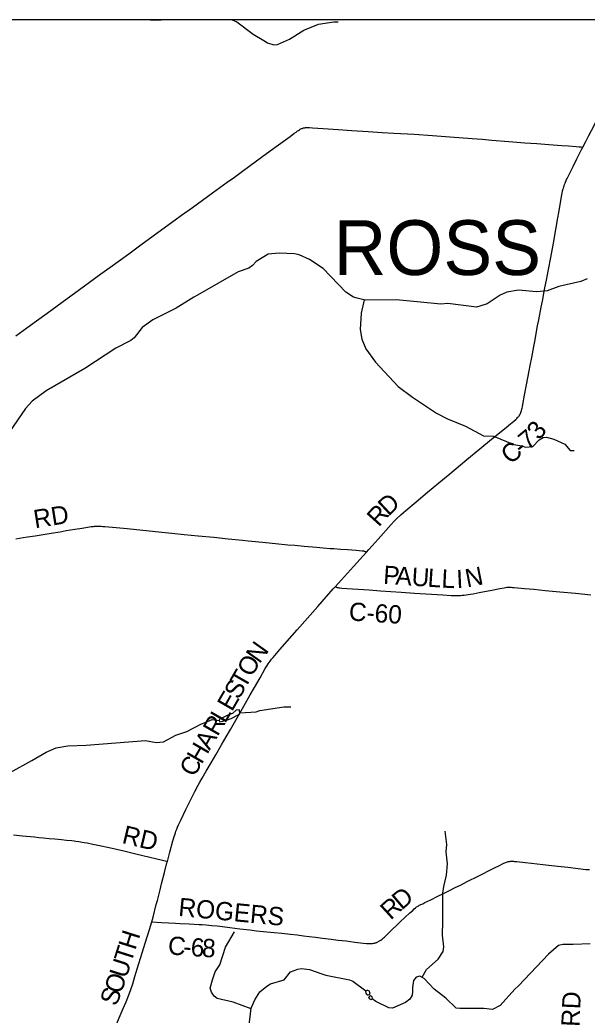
# Model space of a CAD drawing. Extents: x -49 to -8.2, y 9.4 to 23.5.
# Drawn here: x -44.254 to -43.371, y 19.456 to 21.004 of the extents above; entities that cross this region are included whole.
import ezdxf

# ---------------------------------------------------------------- set-up
doc = ezdxf.new("R2010")
doc.units = 0
for name, color, linetype in [('GM_X_Adjacent_County', 7, 'Continuous'), ('GM_X_County_Road', 7, 'Continuous'), ('GM_X_County_Road_Text', 7, 'Continuous'), ('GM_X_Major_River', 7, 'Continuous'), ('GM_X_Minor_Lake', 7, 'Continuous'), ('GM_X_Minor_River', 7, 'Continuous'), ('GM_X_Township', 7, 'Continuous'), ('GM_X_Township_Road', 7, 'Continuous'), ('GM_X_Township_Road_Text', 7, 'Continuous'), ('GM_X_Township_Text', 7, 'Continuous')]:
    doc.layers.add(name, color=color, linetype=linetype)

msp = doc.modelspace()

# ---------------------------------------------------------------- linework, layer by layer
at = {"layer": 'GM_X_Adjacent_County'}
msp.add_lwpolyline([(-42.0989, 21.0039), (-46.2895, 21.0039), (-46.2895, 15.4273)], dxfattribs=at)
at = {"layer": 'GM_X_County_Road'}
for points in [[(-43.378, 20.806), (-43.3735, 20.815), (-43.3689, 20.824), (-43.3607, 20.8398), (-43.3541, 20.8524), (-43.3514, 20.8577), (-43.3468, 20.8665), (-43.3433, 20.8731), (-43.3378, 20.8839), (-43.3284, 20.9017), (-43.3198, 20.918), (-43.3147, 20.9274)], [(-44.2603, 20.5123), (-44.2432, 20.5249), (-44.2282, 20.5358), (-44.2119, 20.5477), (-44.1885, 20.5647), (-44.1612, 20.5847), (-44.1459, 20.5959), (-44.128, 20.6088), (-44.1142, 20.6188), (-44.0976, 20.6308), (-44.0844, 20.6402), (-44.0657, 20.6541), (-44.0275, 20.6819), (-44.0123, 20.6927), (-44.0026, 20.6999), (-43.9855, 20.7123), (-43.9545, 20.7347), (-43.9314, 20.7515), (-43.9203, 20.7594), (-43.9099, 20.7669), (-43.8959, 20.7772), (-43.8779, 20.7904), (-43.8645, 20.8), (-43.8515, 20.8095), (-43.8445, 20.8147), (-43.8337, 20.8226), (-43.8276, 20.8272), (-43.8244, 20.8295), (-43.8234, 20.8303), (-43.8221, 20.8312), (-43.8207, 20.8321), (-43.819, 20.8331), (-43.8178, 20.8338), (-43.8168, 20.8343), (-43.8157, 20.8348), (-43.8147, 20.8352), (-43.8137, 20.8355), (-43.8126, 20.8358), (-43.8117, 20.836), (-43.8107, 20.8362), (-43.8097, 20.8363), (-43.8088, 20.8364), (-43.8076, 20.8364), (-43.8056, 20.8364), (-43.8032, 20.8363), (-43.7986, 20.836), (-43.7821, 20.8348), (-43.7586, 20.8332), (-43.7378, 20.832), (-43.7121, 20.8304), (-43.6904, 20.8289), (-43.6724, 20.8279), (-43.6405, 20.826), (-43.6119, 20.8241), (-43.5853, 20.8221), (-43.5503, 20.8194), (-43.5348, 20.8182), (-43.5196, 20.817), (-43.4933, 20.8149), (-43.4685, 20.8129), (-43.4496, 20.8115), (-43.4311, 20.8102), (-43.4109, 20.8086), (-43.4004, 20.8078), (-43.3883, 20.807), (-43.3839, 20.8066), (-43.3809, 20.8063), (-43.378, 20.806)], [(-43.7146, 20.176), (-43.711, 20.1801), (-43.7058, 20.1858), (-43.6968, 20.1961), (-43.6766, 20.2189), (-43.6719, 20.2239), (-43.6698, 20.2261), (-43.6677, 20.2281), (-43.6615, 20.2338), (-43.6573, 20.2374), (-43.6535, 20.2407), (-43.6374, 20.2543), (-43.6197, 20.2691), (-43.6021, 20.2838), (-43.5851, 20.2979), (-43.5586, 20.3199), (-43.5382, 20.3367), (-43.5201, 20.3514), (-43.4999, 20.3679), (-43.4907, 20.3753), (-43.4878, 20.3777), (-43.4852, 20.3798), (-43.4821, 20.3825), (-43.481, 20.3836), (-43.4795, 20.3851), (-43.4785, 20.3862), (-43.4778, 20.3871), (-43.4771, 20.3881), (-43.4763, 20.3895), (-43.4756, 20.3907), (-43.475, 20.3918), (-43.4744, 20.3933), (-43.4739, 20.3948), (-43.4734, 20.3965), (-43.4729, 20.3982), (-43.4725, 20.3998), (-43.4721, 20.4019), (-43.4714, 20.4056), (-43.4687, 20.4202), (-43.4658, 20.4361), (-43.4617, 20.4581), (-43.4602, 20.4661), (-43.4577, 20.4789), (-43.4545, 20.4957), (-43.4525, 20.5063), (-43.4506, 20.5161), (-43.4484, 20.528), (-43.4466, 20.5375), (-43.4428, 20.557), (-43.4409, 20.5664), (-43.4381, 20.5814), (-43.437, 20.5872), (-43.4348, 20.5991), (-43.4317, 20.6156), (-43.4281, 20.6344), (-43.4239, 20.6568), (-43.4201, 20.6779), (-43.4169, 20.6959), (-43.4154, 20.7045), (-43.4134, 20.7161), (-43.4113, 20.729), (-43.4103, 20.7345), (-43.4097, 20.7376), (-43.4095, 20.7383), (-43.4094, 20.7389), (-43.4091, 20.74), (-43.4087, 20.7413), (-43.4084, 20.7424), (-43.4079, 20.7441), (-43.4073, 20.746), (-43.4066, 20.7479), (-43.4058, 20.75), (-43.4052, 20.7517), (-43.4042, 20.754), (-43.4035, 20.7554), (-43.4027, 20.757), (-43.3978, 20.7667), (-43.3932, 20.7759), (-43.3872, 20.7877), (-43.3799, 20.8022), (-43.378, 20.806)], [(-43.7635, 20.1219), (-43.7539, 20.1326), (-43.7348, 20.1538), (-43.7146, 20.176)], [(-44.0246, 19.6947), (-44.0209, 19.7091), (-44.0161, 19.7265), (-44.0151, 19.73), (-44.014, 19.7333), (-44.0132, 19.736), (-44.0122, 19.739), (-44.0112, 19.7419), (-44.0099, 19.7451), (-44.0087, 19.7482), (-44.0072, 19.7517), (-44.0057, 19.755), (-44.0038, 19.7591), (-43.996, 19.7753), (-43.9876, 19.7923), (-43.982, 19.8037), (-43.9767, 19.8136), (-43.9742, 19.8182), (-43.9706, 19.8245), (-43.9643, 19.8352), (-43.9567, 19.848), (-43.9491, 19.8608), (-43.9404, 19.8759), (-43.9332, 19.8883), (-43.9265, 19.8998), (-43.9162, 19.9179), (-43.9055, 19.9365), (-43.8956, 19.954), (-43.8891, 19.9653), (-43.8804, 19.9804), (-43.8723, 19.9948), (-43.8694, 19.9995), (-43.8678, 20.0019), (-43.8662, 20.0042), (-43.8644, 20.0065), (-43.8624, 20.0092), (-43.8602, 20.012), (-43.8575, 20.0152), (-43.8495, 20.0243), (-43.8226, 20.0548), (-43.7906, 20.0913), (-43.7664, 20.1187), (-43.7635, 20.1219)], [(-43.7635, 20.1219), (-43.7621, 20.1214), (-43.7613, 20.1212), (-43.7604, 20.1209), (-43.7592, 20.1207), (-43.7579, 20.1204), (-43.7564, 20.1202), (-43.7533, 20.1199), (-43.7363, 20.1187), (-43.7108, 20.117), (-43.6929, 20.1157), (-43.6606, 20.1135), (-43.6398, 20.1122), (-43.5958, 20.1093), (-43.5831, 20.1085), (-43.5775, 20.1083), (-43.5755, 20.1084), (-43.5735, 20.1084), (-43.571, 20.1084), (-43.5685, 20.1086), (-43.566, 20.1087), (-43.5629, 20.109), (-43.5598, 20.1094), (-43.5565, 20.1098), (-43.5527, 20.1104), (-43.5488, 20.1111), (-43.5394, 20.113), (-43.5199, 20.1169), (-43.5071, 20.1195), (-43.5007, 20.1206), (-43.4982, 20.121), (-43.4965, 20.1212), (-43.4949, 20.1213), (-43.4931, 20.1214), (-43.4915, 20.1214), (-43.4898, 20.1213), (-43.4873, 20.1211), (-43.4848, 20.1209), (-43.4688, 20.1195), (-43.4542, 20.1181), (-43.4369, 20.1164), (-43.414, 20.1143), (-43.3896, 20.112), (-43.3658, 20.1097)], [(-44.0487, 19.6007), (-44.0338, 19.5997), (-44.0228, 19.599), (-44.0121, 19.5985), (-44.0049, 19.5982), (-43.9906, 19.5975), (-43.9754, 19.5968), (-43.9704, 19.5965), (-43.9645, 19.5961), (-43.9599, 19.5956), (-43.9553, 19.5952), (-43.947, 19.5943), (-43.9388, 19.5933), (-43.9276, 19.592), (-43.9121, 19.59), (-43.8963, 19.5881), (-43.8859, 19.5869), (-43.8696, 19.5853), (-43.8585, 19.5842), (-43.8464, 19.5829), (-43.8337, 19.5816), (-43.8224, 19.5803), (-43.8128, 19.5791), (-43.8038, 19.578), (-43.7942, 19.5767), (-43.7832, 19.5754), (-43.7699, 19.5738), (-43.7586, 19.5724), (-43.7466, 19.571), (-43.733, 19.5693), (-43.72, 19.5678), (-43.7147, 19.5672), (-43.7116, 19.5669), (-43.7093, 19.5668), (-43.7078, 19.5668), (-43.7065, 19.5669), (-43.7052, 19.5671), (-43.704, 19.5674), (-43.7019, 19.5678), (-43.7008, 19.5681), (-43.6997, 19.5685), (-43.6989, 19.5687), (-43.6981, 19.5691), (-43.6971, 19.5695), (-43.6962, 19.57), (-43.6953, 19.5705), (-43.6943, 19.571), (-43.6933, 19.5717), (-43.6922, 19.5724), (-43.6905, 19.5737), (-43.6881, 19.5757), (-43.6865, 19.5771), (-43.6797, 19.5839), (-43.6741, 19.5894), (-43.6682, 19.5952), (-43.6616, 19.6013), (-43.6549, 19.6075), (-43.6473, 19.6146), (-43.6428, 19.6186), (-43.6403, 19.6209), (-43.6385, 19.6223), (-43.6372, 19.6234), (-43.6366, 19.6239), (-43.6358, 19.6244), (-43.6345, 19.6253), (-43.6332, 19.626), (-43.6304, 19.6275), (-43.6272, 19.629), (-43.6239, 19.6307), (-43.6148, 19.6351), (-43.605, 19.64), (-43.595, 19.6449), (-43.5856, 19.6497), (-43.5767, 19.6541), (-43.5686, 19.658), (-43.5579, 19.6634), (-43.541, 19.6719), (-43.5338, 19.6754), (-43.5249, 19.6799), (-43.5144, 19.6851), (-43.5086, 19.6881), (-43.5011, 19.6919), (-43.4997, 19.6925), (-43.4982, 19.6931), (-43.4969, 19.6936), (-43.4955, 19.6941), (-43.4942, 19.6944), (-43.4936, 19.6945), (-43.4931, 19.6946), (-43.492, 19.6948), (-43.4907, 19.6949), (-43.4895, 19.695), (-43.4885, 19.695), (-43.4876, 19.695), (-43.486, 19.6949), (-43.4845, 19.6948), (-43.4834, 19.6948), (-43.4807, 19.6946), (-43.4678, 19.6932), (-43.4581, 19.6921), (-43.4405, 19.6901), (-43.4171, 19.6874), (-43.4014, 19.6856), (-43.3853, 19.6838), (-43.3733, 19.6824), (-43.3675, 19.6819)], [(-44.0487, 19.6007), (-44.0469, 19.6078), (-44.0418, 19.6276), (-44.0402, 19.634), (-44.038, 19.6423), (-44.0359, 19.6503), (-44.0335, 19.6599), (-44.0291, 19.6773), (-44.0252, 19.6926), (-44.0246, 19.6947)], [(-44.1213, 19.4002), (-44.114, 19.4176), (-44.1069, 19.4342), (-44.0932, 19.4658), (-44.0888, 19.4764), (-44.0852, 19.4857), (-44.0817, 19.4953), (-44.0786, 19.5045), (-44.0752, 19.5157), (-44.071, 19.5294), (-44.059, 19.5673), (-44.0524, 19.5887), (-44.0487, 19.6007)]]:
    msp.add_lwpolyline(points, dxfattribs=at)
at = {"layer": 'GM_X_Major_River'}
for points in [[(-43.3669, 19.5666), (-43.3929, 19.5654), (-43.4093, 19.5655), (-43.416, 19.5641), (-43.4314, 19.5506), (-43.4784, 19.501), (-43.4839, 19.4958), (-43.5068, 19.4705), (-43.5188, 19.4643), (-43.5322, 19.466), (-43.5693, 19.4657), (-43.5751, 19.4662), (-43.5915, 19.4822), (-43.6095, 19.4959), (-43.6249, 19.5127), (-43.6318, 19.5163), (-43.6375, 19.5149), (-43.6418, 19.5095), (-43.643, 19.4987), (-43.6431, 19.4922), (-43.6438, 19.4867), (-43.6473, 19.4805), (-43.654, 19.475), (-43.6741, 19.4664), (-43.6799, 19.4669), (-43.7004, 19.4767), (-43.7061, 19.4808)], [(-43.9634, 19.3196), (-43.9479, 19.336), (-43.9178, 19.3778), (-43.9116, 19.3915), (-43.9093, 19.4028), (-43.9058, 19.41), (-43.9053, 19.4153), (-43.8977, 19.4358), (-43.8943, 19.4662), (-43.8887, 19.4795), (-43.8805, 19.4917), (-43.8697, 19.5004), (-43.864, 19.5041), (-43.8427, 19.5107), (-43.8332, 19.523), (-43.8217, 19.5272), (-43.8157, 19.528), (-43.8036, 19.5268), (-43.7844, 19.5196), (-43.778, 19.5177), (-43.7411, 19.5105), (-43.7362, 19.5085), (-43.7159, 19.4933)], [(-43.7159, 19.4933), (-43.7163, 19.4919), (-43.716, 19.4899), (-43.7149, 19.4884), (-43.7136, 19.4872), (-43.7119, 19.4872), (-43.71, 19.4879), (-43.7092, 19.4892), (-43.7093, 19.4909), (-43.7101, 19.4928), (-43.7115, 19.4935), (-43.7127, 19.4938), (-43.714, 19.4938), (-43.7144, 19.4937)], [(-43.7159, 19.4933), (-43.7144, 19.4937)], [(-43.7116, 19.4832), (-43.711, 19.4824), (-43.7099, 19.481), (-43.7086, 19.4802), (-43.7075, 19.48), (-43.7065, 19.4804), (-43.7059, 19.481), (-43.7053, 19.4827), (-43.7057, 19.484), (-43.7072, 19.4848), (-43.7087, 19.4854), (-43.7095, 19.4852)], [(-43.7095, 19.4852), (-43.7116, 19.4832)]]:
    msp.add_lwpolyline(points, dxfattribs=at)
at = {"layer": 'GM_X_Minor_Lake'}
for points in [[(-43.9429, 19.9117), (-43.9326, 19.9143), (-43.9253, 19.917), (-43.9146, 19.9226), (-43.9116, 19.9246), (-43.9124, 19.9307), (-43.9177, 19.93), (-43.9235, 19.9246), (-43.9304, 19.9223), (-43.9386, 19.9182), (-43.9428, 19.9162)], [(-43.9428, 19.9162), (-43.9434, 19.9156), (-43.9438, 19.9145), (-43.9436, 19.9126), (-43.9429, 19.9117)], [(-43.9634, 19.3196), (-43.9479, 19.336), (-43.9178, 19.3778), (-43.9116, 19.3915), (-43.9093, 19.4028), (-43.9058, 19.41), (-43.9053, 19.4153), (-43.8977, 19.4358), (-43.8943, 19.4662), (-43.8887, 19.4795), (-43.8805, 19.4917), (-43.8697, 19.5004), (-43.864, 19.5041), (-43.8427, 19.5107), (-43.8332, 19.523), (-43.8217, 19.5272), (-43.8157, 19.528), (-43.8036, 19.5268), (-43.7844, 19.5196), (-43.778, 19.5177), (-43.7411, 19.5105), (-43.7362, 19.5085), (-43.7159, 19.4933)]]:
    msp.add_lwpolyline(points, dxfattribs=at)
at = {"layer": 'GM_X_Minor_River'}
for points in [[(-44.0516, 21.0039), (-44.0464, 21.0033), (-44.0342, 21.0039)], [(-43.9237, 21.0039), (-43.9165, 21.0009), (-43.8909, 20.9819), (-43.8746, 20.9719), (-43.869, 20.968), (-43.8588, 20.9653), (-43.8533, 20.9654), (-43.8347, 20.974), (-43.8121, 20.9882), (-43.7892, 20.9975), (-43.7657, 21.001), (-43.7587, 21.0007)], [(-43.3715, 20.6009), (-43.3812, 20.5967), (-43.4153, 20.5889), (-43.4334, 20.5823), (-43.4503, 20.5809), (-43.4783, 20.5835), (-43.4965, 20.5802), (-43.5066, 20.5756), (-43.527, 20.5623), (-43.5382, 20.5584), (-43.5433, 20.5569), (-43.5881, 20.5627), (-43.5992, 20.5619), (-43.6309, 20.565), (-43.6686, 20.5682), (-43.7163, 20.5679), (-43.7231, 20.5694), (-43.7293, 20.5712), (-43.7352, 20.5724), (-43.7468, 20.5804), (-43.782, 20.6173), (-43.8035, 20.631), (-43.8193, 20.6385), (-43.8267, 20.6402), (-43.8507, 20.641), (-43.8676, 20.6396), (-43.8864, 20.6278), (-43.8923, 20.6218), (-43.8981, 20.6176), (-43.9147, 20.6118), (-43.9777, 20.5757), (-43.9832, 20.5728), (-44.0108, 20.5553), (-44.047, 20.5371), (-44.0638, 20.5255), (-44.0761, 20.5093), (-44.0813, 20.5049), (-44.1046, 20.4932), (-44.1533, 20.4618), (-44.2132, 20.427), (-44.2349, 20.4106), (-44.2455, 20.3996), (-44.2704, 20.3629)], [(-43.7186, 20.5684), (-43.7228, 20.5475), (-43.7245, 20.5223), (-43.7221, 20.5074), (-43.7156, 20.4923), (-43.7006, 20.4715), (-43.6657, 20.4334), (-43.6434, 20.4171), (-43.606, 20.3921), (-43.5889, 20.3834), (-43.5608, 20.3721), (-43.5329, 20.3569), (-43.5172, 20.3562), (-43.4857, 20.3435), (-43.4729, 20.3414), (-43.4673, 20.3392), (-43.4559, 20.3401), (-43.446, 20.3508), (-43.4397, 20.3544), (-43.4348, 20.3547), (-43.4233, 20.3515), (-43.4063, 20.3441), (-43.3978, 20.3341), (-43.3917, 20.334)], [(-43.9118, 19.926), (-43.8865, 19.9274), (-43.8806, 19.9295), (-43.8432, 19.9353), (-43.8324, 19.9353)], [(-44.4085, 19.7863), (-44.3863, 19.7917), (-44.3355, 19.817), (-44.3229, 19.8213), (-44.2694, 19.8331), (-44.2354, 19.8518), (-44.2133, 19.8647), (-44.1979, 19.8715), (-44.1794, 19.8748), (-44.1512, 19.8754), (-44.0584, 19.883), (-44.042, 19.8798), (-44.0304, 19.881), (-44.0113, 19.8913), (-43.9945, 19.897), (-43.9715, 19.9086), (-43.9656, 19.9106), (-43.9551, 19.9155), (-43.9437, 19.9141)], [(-43.6282, 19.5144), (-43.6212, 19.5267), (-43.6033, 19.5425), (-43.5955, 19.5545), (-43.5946, 19.5621), (-43.5965, 19.5802), (-43.5962, 19.6011), (-43.5958, 19.6452), (-43.5946, 19.6558), (-43.5901, 19.6732), (-43.5887, 19.691), (-43.5906, 19.7097), (-43.5899, 19.7209), (-43.5925, 19.7416)], [(-43.8943, 19.4656), (-43.9222, 19.4759), (-43.9469, 19.4817), (-43.9518, 19.485), (-43.9562, 19.4912), (-43.9578, 19.4977), (-43.9544, 19.5105), (-43.9502, 19.5228), (-43.943, 19.5337), (-43.9342, 19.5613), (-43.9203, 19.585)]]:
    msp.add_lwpolyline(points, dxfattribs=at)
at = {"layer": 'GM_X_Township'}
msp.add_line((-42.0989, 21.0039), (-44.9675, 21.0039), dxfattribs=at)
at = {"layer": 'GM_X_Township_Road'}
for points in [[(-44.2605, 20.1965), (-44.2488, 20.1985), (-44.2424, 20.1995), (-44.2304, 20.2015), (-44.2178, 20.2035), (-44.2056, 20.2054), (-44.1915, 20.2077), (-44.182, 20.2093), (-44.1688, 20.2115), (-44.1571, 20.2134), (-44.1431, 20.2156), (-44.1412, 20.2158), (-44.1395, 20.216), (-44.1381, 20.2162), (-44.1369, 20.2162), (-44.1357, 20.2163), (-44.134, 20.2163), (-44.1322, 20.2163), (-44.1299, 20.2163), (-44.1275, 20.2162), (-44.1249, 20.216), (-44.122, 20.2158), (-44.1043, 20.2141), (-44.0873, 20.2125), (-44.0626, 20.21), (-44.028, 20.2065), (-44.0178, 20.2055), (-43.9986, 20.2035), (-43.9766, 20.2014), (-43.9525, 20.199), (-43.93, 20.1968), (-43.9077, 20.1945), (-43.8991, 20.1936), (-43.8932, 20.193), (-43.8876, 20.1925), (-43.8713, 20.1907), (-43.8561, 20.1892), (-43.8369, 20.1875), (-43.8265, 20.1865), (-43.8115, 20.1852), (-43.7928, 20.1836), (-43.782, 20.1827), (-43.7712, 20.1818), (-43.7657, 20.1814), (-43.755, 20.1807), (-43.7441, 20.1799), (-43.731, 20.1789), (-43.7216, 20.178), (-43.7204, 20.1779), (-43.7195, 20.1777), (-43.7184, 20.1775), (-43.7177, 20.1773), (-43.7161, 20.1767), (-43.7146, 20.176)], [(-44.2642, 19.7363), (-44.25, 19.7347), (-44.2312, 19.7328), (-44.2247, 19.7321), (-44.2173, 19.7315), (-44.2086, 19.7306), (-44.1996, 19.7297), (-44.1894, 19.7287), (-44.1817, 19.728), (-44.1733, 19.7271), (-44.1697, 19.7267), (-44.1669, 19.7263), (-44.1625, 19.7257), (-44.16, 19.7254), (-44.157, 19.7249), (-44.1539, 19.7244), (-44.1493, 19.7235), (-44.1405, 19.7217), (-44.1302, 19.7195), (-44.1153, 19.7162), (-44.0926, 19.711), (-44.0738, 19.7067), (-44.0626, 19.7041), (-44.0323, 19.6966), (-44.0283, 19.6956), (-44.0246, 19.6947)]]:
    msp.add_lwpolyline(points, dxfattribs=at)

# ---------------------------------------------------------------- texts
at = {"layer": 'GM_X_County_Road_Text'}
for s, height, rotation, p in [('3', 0.0284, 50.5743, (-43.446, 20.349)), ('7', 0.0284, 39.4159, (-43.4638, 20.3336)), ('C', 0.0284, 39.1584, (-43.4911, 20.3114)), ('-', 0.0284, 39.1877, (-43.473, 20.3261)), ('D', 0.0284, 42.9801, (-43.6806, 20.2309)), ('R', 0.0284, 48.0041, (-43.6957, 20.214)), ('P', 0.0284, 356.215, (-43.6893, 20.1267)), ('A', 0.0284, 356.2123, (-43.6702, 20.1255)), ('U', 0.0284, 356.2149, (-43.6452, 20.1238)), ('L', 0.0284, 356.2486, (-43.6203, 20.1222)), ('L', 0.0284, 357.1496, (-43.5986, 20.1208)), ('I', 0.0284, 2.7323, (-43.5743, 20.1197)), ('N', 0.0284, 11.0056, (-43.5582, 20.1208)), ('C-60', 0.02841, 356.23, (-43.7428, 20.0697)), ('N', 0.0284, 54.583, (-43.8812, 20.0012)), ('O', 0.0284, 59.9971, (-43.8934, 19.9802)), ('T', 0.0284, 60.0444, (-43.904, 19.9618)), ('S', 0.0284, 60.0394, (-43.9135, 19.9452)), ('E', 0.0284, 60.0444, (-43.9241, 19.9267)), ('L', 0.0284, 60.0444, (-43.9348, 19.9083)), ('R', 0.0284, 60.0397, (-43.9464, 19.8881)), ('H', 0.0284, 60.0416, (-43.9714, 19.8448)), ('A', 0.0284, 60.0416, (-43.9589, 19.8665)), ('C', 0.0284, 60.0416, (-43.983, 19.8246)), ('D', 0.0284, 40.188, (-43.6601, 19.6181)), ('ROGERS', 0.02841, 354.5149, (-44.0083, 19.6101)), ('R', 0.0284, 42.3635, (-43.6772, 19.6026)), ('H', 0.0284, 72.4106, (-44.0745, 19.5557)), ('C', 0.0284, 354.9625, (-44.0246, 19.5504)), ('6', 0.0284, 356.3314, (-43.9889, 19.5475)), ('8', 0.0284, 356.4951, (-43.9714, 19.5464)), ('T', 0.0284, 72.4159, (-44.081, 19.5354)), ('-', 0.0284, 356.307, (-44.0006, 19.5483)), ('U', 0.0284, 72.4, (-44.0885, 19.5116)), ('O', 0.0284, 71.4026, (-44.0967, 19.4874)), ('S', 0.0284, 68.6203, (-44.1042, 19.4681))]:
    msp.add_text(s, height=height, rotation=rotation, dxfattribs=at).set_placement(p)
at = {"layer": 'GM_X_Township_Road_Text'}
for rotation, p in [(9.1413, (-44.2305, 20.2129)), (346.6748, (-44.0966, 19.7235)), (87.6543, (-43.3833, 19.4371))]:
    msp.add_text('RD', height=0.02841, rotation=rotation, dxfattribs=at).set_placement(p)
at = {"layer": 'GM_X_Township_Text'}
msp.add_text('ROSS', height=0.08523, rotation=0, dxfattribs=at).set_placement((-43.7661, 20.607))

doc.saveas('drawing.dxf')
